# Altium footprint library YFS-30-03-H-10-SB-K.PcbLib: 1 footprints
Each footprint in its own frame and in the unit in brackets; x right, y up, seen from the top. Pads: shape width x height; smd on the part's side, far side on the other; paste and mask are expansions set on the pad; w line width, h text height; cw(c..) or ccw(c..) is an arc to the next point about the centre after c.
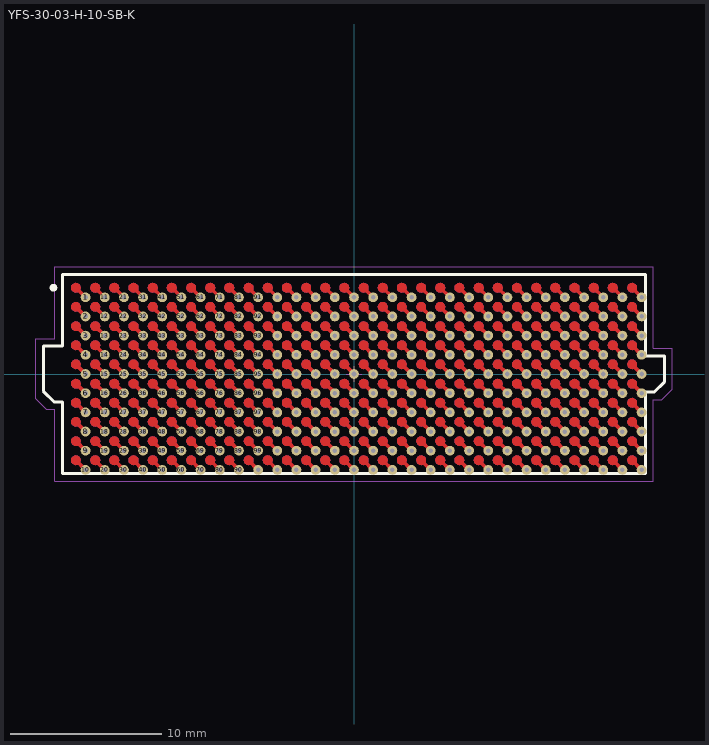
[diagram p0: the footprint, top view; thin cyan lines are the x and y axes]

## YFS-30-03-H-10-SB-K [mm] "1.27mm pitch, 300 pin, SamArray socket strip"
height 3.4
pads (300):
  round 0.65 hole 0.3 unplated mask+0: 1(-17.78,5.08) 2(-17.78,3.81) 3(-17.78,2.54) 4(-17.78,1.27) 5(-17.78,0) 6(-17.78,-1.27) 7(-17.78,-2.54) 8(-17.78,-3.81) 9(-17.78,-5.08) 10(-17.78,-6.35) 11(-16.51,5.08) 12(-16.51,3.81) 13(-16.51,2.54) 14(-16.51,1.27) 15(-16.51,0) 16(-16.51,-1.27) 17(-16.51,-2.54) 18(-16.51,-3.81) 19(-16.51,-5.08) 20(-16.51,-6.35) 21(-15.24,5.08) 22(-15.24,3.81) 23(-15.24,2.54) 24(-15.24,1.27) 25(-15.24,0) 26(-15.24,-1.27) 27(-15.24,-2.54) 28(-15.24,-3.81) 29(-15.24,-5.08) 30(-15.24,-6.35) 31(-13.97,5.08) 32(-13.97,3.81) 33(-13.97,2.54) 34(-13.97,1.27) 35(-13.97,0) 36(-13.97,-1.27) 37(-13.97,-2.54) 38(-13.97,-3.81) 39(-13.97,-5.08) 40(-13.97,-6.35) 41(-12.7,5.08) 42(-12.7,3.81) 43(-12.7,2.54) 44(-12.7,1.27) 45(-12.7,0) 46(-12.7,-1.27) 47(-12.7,-2.54) 48(-12.7,-3.81) 49(-12.7,-5.08) 50(-12.7,-6.35) 51(-11.43,5.08) 52(-11.43,3.81) 53(-11.43,2.54) 54(-11.43,1.27) 55(-11.43,0) 56(-11.43,-1.27) 57(-11.43,-2.54) 58(-11.43,-3.81) 59(-11.43,-5.08) 60(-11.43,-6.35) 61(-10.16,5.08) 62(-10.16,3.81) 63(-10.16,2.54) 64(-10.16,1.27) 65(-10.16,0) 66(-10.16,-1.27) 67(-10.16,-2.54) 68(-10.16,-3.81) 69(-10.16,-5.08) 70(-10.16,-6.35) 71(-8.89,5.08) 72(-8.89,3.81) 73(-8.89,2.54) 74(-8.89,1.27) 75(-8.89,0) 76(-8.89,-1.27) 77(-8.89,-2.54) 78(-8.89,-3.81) 79(-8.89,-5.08) 80(-8.89,-6.35) 81(-7.62,5.08) 82(-7.62,3.81) 83(-7.62,2.54) 84(-7.62,1.27) 85(-7.62,0) 86(-7.62,-1.27) 87(-7.62,-2.54) 88(-7.62,-3.81) 89(-7.62,-5.08) 90(-7.62,-6.35) 91(-6.35,5.08) 92(-6.35,3.81) 93(-6.35,2.54) 94(-6.35,1.27) 95(-6.35,0) 96(-6.35,-1.27) 97(-6.35,-2.54) 98(-6.35,-3.81) 99(-6.35,-5.08) 100(-6.35,-6.35) 101(-5.08,5.08) 102(-5.08,3.81) 103(-5.08,2.54) 104(-5.08,1.27) 105(-5.08,0) 106(-5.08,-1.27) 107(-5.08,-2.54) 108(-5.08,-3.81) 109(-5.08,-5.08) 110(-5.08,-6.35) 111(-3.81,5.08) 112(-3.81,3.81) 113(-3.81,2.54) 114(-3.81,1.27) 115(-3.81,0) 116(-3.81,-1.27) 117(-3.81,-2.54) 118(-3.81,-3.81) 119(-3.81,-5.08) 120(-3.81,-6.35) 121(-2.54,5.08) 122(-2.54,3.81) 123(-2.54,2.54) 124(-2.54,1.27) 125(-2.54,0) 126(-2.54,-1.27) 127(-2.54,-2.54) 128(-2.54,-3.81) 129(-2.54,-5.08) 130(-2.54,-6.35) 131(-1.27,5.08) 132(-1.27,3.81) 133(-1.27,2.54) 134(-1.27,1.27) 135(-1.27,0) 136(-1.27,-1.27) 137(-1.27,-2.54) 138(-1.27,-3.81) 139(-1.27,-5.08) 140(-1.27,-6.35) 141(0,5.08) 142(0,3.81) 143(0,2.54) 144(0,1.27) 145(0,0) 146(0,-1.27) 147(0,-2.54) 148(0,-3.81) 149(0,-5.08) 150(0,-6.35) 151(1.27,5.08) 152(1.27,3.81) 153(1.27,2.54) 154(1.27,1.27) 155(1.27,0) 156(1.27,-1.27) 157(1.27,-2.54) 158(1.27,-3.81) 159(1.27,-5.08) 160(1.27,-6.35) 161(2.54,5.08) 162(2.54,3.81) 163(2.54,2.54) 164(2.54,1.27) 165(2.54,0) 166(2.54,-1.27) 167(2.54,-2.54) 168(2.54,-3.81) 169(2.54,-5.08) 170(2.54,-6.35) 171(3.81,5.08) 172(3.81,3.81) 173(3.81,2.54) 174(3.81,1.27) 175(3.81,0) 176(3.81,-1.27) 177(3.81,-2.54) 178(3.81,-3.81) 179(3.81,-5.08) 180(3.81,-6.35) 181(5.08,5.08) 182(5.08,3.81) 183(5.08,2.54) 184(5.08,1.27) 185(5.08,0) 186(5.08,-1.27) 187(5.08,-2.54) 188(5.08,-3.81) 189(5.08,-5.08) 190(5.08,-6.35) 191(6.35,5.08) 192(6.35,3.81) 193(6.35,2.54) 194(6.35,1.27) 195(6.35,0) 196(6.35,-1.27) 197(6.35,-2.54) 198(6.35,-3.81) 199(6.35,-5.08) 200(6.35,-6.35) 201(7.62,5.08) 202(7.62,3.81) 203(7.62,2.54) 204(7.62,1.27) 205(7.62,0) 206(7.62,-1.27) 207(7.62,-2.54) 208(7.62,-3.81) 209(7.62,-5.08) 210(7.62,-6.35) 211(8.89,5.08) 212(8.89,3.81) 213(8.89,2.54) 214(8.89,1.27) 215(8.89,0) 216(8.89,-1.27) 217(8.89,-2.54) 218(8.89,-3.81) 219(8.89,-5.08) 220(8.89,-6.35) 221(10.16,5.08) 222(10.16,3.81) 223(10.16,2.54) 224(10.16,1.27) 225(10.16,0) 226(10.16,-1.27) 227(10.16,-2.54) 228(10.16,-3.81) 229(10.16,-5.08) 230(10.16,-6.35) 231(11.43,5.08) 232(11.43,3.81) 233(11.43,2.54) 234(11.43,1.27) 235(11.43,0) 236(11.43,-1.27) 237(11.43,-2.54) 238(11.43,-3.81) 239(11.43,-5.08) 240(11.43,-6.35) 241(12.7,5.08) 242(12.7,3.81) 243(12.7,2.54) 244(12.7,1.27) 245(12.7,0) 246(12.7,-1.27) 247(12.7,-2.54) 248(12.7,-3.81) 249(12.7,-5.08) 250(12.7,-6.35) 251(13.97,5.08) 252(13.97,3.81) 253(13.97,2.54) 254(13.97,1.27) 255(13.97,0) 256(13.97,-1.27) 257(13.97,-2.54) 258(13.97,-3.81) 259(13.97,-5.08) 260(13.97,-6.35) 261(15.24,5.08) 262(15.24,3.81) 263(15.24,2.54) 264(15.24,1.27) 265(15.24,0) 266(15.24,-1.27) 267(15.24,-2.54) 268(15.24,-3.81) 269(15.24,-5.08) 270(15.24,-6.35) 271(16.51,5.08) 272(16.51,3.81) 273(16.51,2.54) 274(16.51,1.27) 275(16.51,0) 276(16.51,-1.27) 277(16.51,-2.54) 278(16.51,-3.81) 279(16.51,-5.08) 280(16.51,-6.35) 281(17.78,5.08) 282(17.78,3.81) 283(17.78,2.54) 284(17.78,1.27) 285(17.78,0) 286(17.78,-1.27) 287(17.78,-2.54) 288(17.78,-3.81) 289(17.78,-5.08) 290(17.78,-6.35) 291(19.05,5.08) 292(19.05,3.81) 293(19.05,2.54) 294(19.05,1.27) 295(19.05,0) 296(19.05,-1.27) 297(19.05,-2.54) 298(19.05,-3.81) 299(19.05,-5.08) 300(19.05,-6.35)
Top Layer:
  drawing of 600 lines, arcs and shapes, not listed
Top Overlay:
  circle w0.25: c-19.905,5.715 r0.125
  lines w0.2: -20.575,-1.14 -19.875,-1.84 -19.305,-1.84 -19.305,-6.605 19.305,-6.605 19.305,-1.205 19.875,-1.205 20.575,-0.505 20.575,1.205 19.305,1.205 19.305,6.605 -19.305,6.605 -19.305,1.84 -20.575,1.84 -20.575,-1.14
Top Paste:
  drawing of 300 lines, arcs and shapes, not listed
Top Solder:
  drawing of 300 lines, arcs and shapes, not listed
Mechanical 12:
  lines w0.001: -20.575,-1.14 -19.875,-1.84 -19.305,-1.84 -19.305,-6.605 19.305,-6.605 19.305,-1.205 19.875,-1.205 20.575,-0.505 20.575,1.205 19.305,1.205 19.305,6.605 -19.305,6.605 -19.305,1.84 -20.575,1.84 -20.575,-1.14
Mechanical 13:
  drawing of 314 lines, arcs and shapes, not listed
  text ".Designator" at 0,0 h1.52
Mechanical 15:
  lines w0.005: -21.075,-1.64 -20.375,-2.34 -19.805,-2.34 -19.805,-7.105 19.805,-7.105 19.805,-1.705 20.375,-1.705 21.075,-1.005 21.075,1.705 19.805,1.705 19.805,7.105 -19.805,7.105 -19.805,2.34 -21.075,2.34 -21.075,-1.64
  lines w0.05: -0.5,0 0.5,0 ; 0,-0.5 0,0.5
